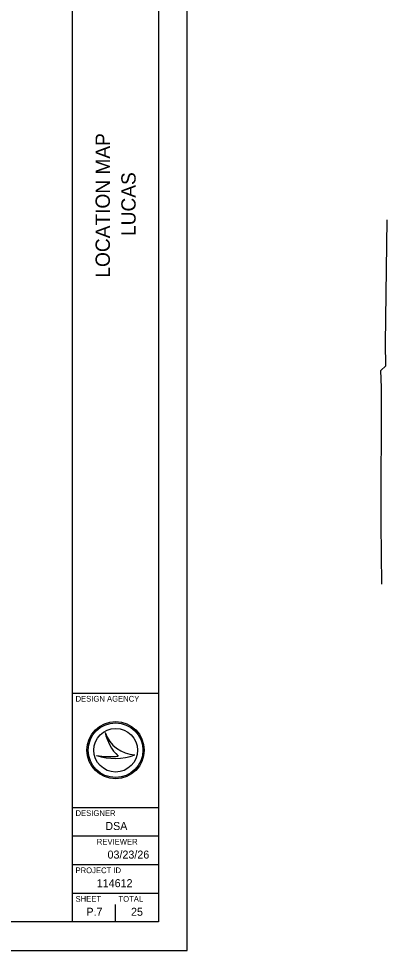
# Model space of a CAD drawing. Extents: x 0 to 750, y 0 to 507.
# Drawn here: x 621.1 to 749.9, y 0 to 325.9 of the extents above; entities that cross this region are included whole.
import ezdxf

# ---------------------------------------------------------------- set-up
doc = ezdxf.new("R2010")
doc.units = 0
for name, color, linetype in [('GM_P_US_Alignment', 7, 'Continuous'), ('SH_Border', 7, 'Continuous'), ('SH_Cut_Line', 7, 'Continuous'), ('SH_Data', 7, 'Continuous')]:
    doc.layers.add(name, color=color, linetype=linetype)

msp = doc.modelspace()

# ---------------------------------------------------------------- linework, layer by layer
at = {"layer": 'GM_P_US_Alignment'}
msp.add_lwpolyline([(747.95, 128.11), (747.81, 149.09), (747.85, 196.83), (747.64, 202.82), (749.35, 204.39), (749.32, 212.29), (749.92, 255.48)], dxfattribs=at)
at = {"layer": 'SH_Border'}
for p, q in [((640, 10), (640, 430)), ((640, 90), (670, 90)), ((640, 50), (670, 50)), ((640, 40), (670, 40)), ((640, 30), (670, 30)), ((640, 20), (670, 20))]:
    msp.add_line(p, q, dxfattribs=at)
msp.add_lwpolyline([(30, 430), (670, 430), (670, 10), (30, 10)], close=True, dxfattribs=at)
at = {"layer": 'SH_Cut_Line'}
msp.add_lwpolyline([(0, 0), (680, 0), (680, 440), (0, 440)], close=True, dxfattribs=at)
at = {"layer": 'SH_Data'}
for p, q in [((651.35, 76.19), (651.35, 76.19)), ((655, 70), (655, 70)), ((648.34, 68.19), (648.34, 68.19)), ((661.75, 68.37), (661.75, 68.37)), ((647.5, 13.5), (647.5, 13.5)), ((655, 10), (655, 16))]:
    msp.add_line(p, q, dxfattribs=at)
for radius in [10, 9.54, 9.54, 7.64]:
    msp.add_circle((655, 70), radius, dxfattribs=at)
for centre, radius, start, end in [((662.32, 79.95), 11.6, 198.9257, 198.9319), ((666.93, 79.4), 15.91, 191.6379, 191.6421), ((662.32, 79.95), 11.6, 198.9319, 267.1657), ((666.93, 79.4), 15.91, 191.6421, 226.0947), ((654.79, 87.4), 20.26, 251.4576, 290.0832), ((652.96, 93.09), 25.32, 259.4964, 259.4995), ((654.79, 87.4), 20.26, 251.4527, 251.4576), ((652.96, 93.09), 25.32, 259.4995, 276.6672)]:
    msp.add_arc(centre, radius, start, end, dxfattribs=at)

# ---------------------------------------------------------------- texts
for s, p in [('LOCATION MAP', (653, 235.29)), ('LUCAS', (662, 249.85))]:
    msp.add_text(s, height=5, rotation=90, dxfattribs=at).set_placement(p)
for s, height, p in [('DESIGN AGENCY', 2, (641, 87)), ('DESIGNER', 2, (641, 47)), ('DSA', 2.8, (651.41, 42.1)), ('REVIEWER', 2, (648.44, 37)), ('03/23/26', 2.8, (652.18, 32.1)), ('PROJECT ID', 2, (641, 27)), ('114612', 2.8, (648.42, 22.1)), ('SHEET', 2, (641, 17)), ('TOTAL', 2, (656, 17)), ('P.7', 2.8, (644.79, 12.1)), ('25', 2.8, (660.39, 12.1))]:
    msp.add_text(s, height=height, dxfattribs=at).set_placement(p)

doc.saveas('drawing.dxf')
